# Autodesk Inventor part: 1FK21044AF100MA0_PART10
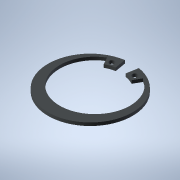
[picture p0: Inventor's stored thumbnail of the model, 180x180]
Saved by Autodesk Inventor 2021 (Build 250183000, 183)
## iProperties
Created: 2025-04
Part Number: 1FK21044AF100MA0_PART10
Material: Generic
Catalog Web Link: www.3dfindit.com
Description: -Servo synchronous motor
Document SubType Name: Modeling
Designer: psAdmin
Mass: 0.642463 g
Surface Area: 12.3927 cm^2
Volume: 0.642463 cm^3
Density: 1 g/cm^3
Appearance: PSOLRGB-212-217-219
Category: PARTsolutions
Title: 1FK21044AF100MA0_PART10
Author: Cadenas PARTsolutions
Comments: Servo synchronous motor
Sending System: PARTsolutions
Preprocessor: ST-DEVELOPER v19.3
PSOL_IDENT_0: {$CADENAS_DATA/23d-libs/siemens_ag/_cat_/ec/e4/1fk21044af100ma0.prj},216 {VTYP=3D},{NB=1FK21044AF100
PSOL_IDENT_1: MA0_PART10},{LINA=1FK21044AF100MA0_PART10},{NN=1FK21044AF100MA0_PART10},{NOPRJ=TRUE},{DATE=19.08.202
PSOL_IDENT_2: 5 14:01:05},{GEOMDATE=30.07.2025 02:01:01},{VERSION=},{LINEID=10},{WBVAR=},{WBNUMERIC=}  {NB=1FK2104
PSOL_IDENT_3: 4AF100MA0_PART10},{LINA=1FK21044AF100MA0_PART10},{KT=DUMMY},{PREVIEW=../../../_pool_/cb/72/p_d211_xx
PSOL_IDENT_4: _00434j.png},{DESCSHORT=SIMOTICS S-1FK2 HD, SINAMICS S210 3AC 400V-480V, 1.27 Nm, 3000 rpm},{DESCLON
PSOL_IDENT_5: G=SIMOTICS S-1FK2 HD servo motor M0=1.27 Nm; PN = 0.4 kW at nN=3000 rpm (380-480 V); PN = 0.2 kW at
PSOL_IDENT_6: nN=1500 rpm (200-240 V); with holding brake; degree of protection IP64; cylindrical shaft D19x40mm;
PSOL_IDENT_7: absolute encoder 22-bit + 12-bit multiturn (encoder AM22DQC); with OCC interface; plug size M17, rot
PSOL_IDENT_8: atable; SIMOTICS S-1FK2 servomotorfor a wide range of uses in industrial environments. SIMOTICS S‑1F
PSOL_IDENT_9: K2 servomotors are compact synchronous motors with a high dynamic performance that set themselves ap
PSOL_IDENT_10: art as a result of their high power density, degree of protection and overload capability. The motor
PSOL_IDENT_11: s are available in two variants: as High Dynamic variant (highest dynamic performance as a result of
PSOL_IDENT_12: the low intrinsic moment of inertia for applications demanding a high dynamic performance with low
PSOL_IDENT_13: moved masses) - and as Compact variant (precise and stable closed-loop control for medium up to larg
PSOL_IDENT_14: e moved masses as a result of a medium intrinsic moment of inertia). SIMOTICSS‑1FK2 servomotors full
PSOL_IDENT_15: y exploit their strengths in a system with the SINAMICSS210 frequency converter and simple connectio
PSOL_IDENT_16: n using the one cable connection (OCC). Advantages include the short control and positioning times,
PSOL_IDENT_17: fast and precise correction of disturbing quantities as well as stable control with a high dynamic p
PSOL_IDENT_18: erformance. The servo motors can be configured to address a wide range of requirements. For example
PSOL_IDENT_19: with and without holding brake, IP64 or IP65 degree of protection, singleturn or multiturn absolute
PSOL_IDENT_20: encoders - to name just a few. Further, the servomotors are available in different shaft heights ext
PSOL_IDENT_21: ending from 20 to 100. A shaft sealing ring is available to achieve an IP65 degree of protection and
PSOL_IDENT_22: for subsequent mounting at the motor or as spare part. SIMOTICS - the optimum motor for each and ev
PSOL_IDENT_23: ery motion control application.},{INTNO=195125043275},{SUPPLIERALTNO=1FK2104-4AF10-0MA0},{MANUID=1FK
PSOL_IDENT_24: 21044AF100MA0},{MANUNAME=Siemens},{MANUTYPEDESC=Synchronous motor 1FK2-HD 1.27 NM},{AAU732=SIMOTICS}
PSOL_IDENT_25: ,{AAO057=S-1FK2},{AAU734=SIMOTICS S-1FK2 HD servo motor M0=1.27 Nm; PN = 0.4 kW at nN=3000 rpm (380-
PSOL_IDENT_26: 480 V); PN = 0.2 kW at nN=1500 rpm (200-240 V); with holding brake; degree of protection IP64; cylin
PSOL_IDENT_27: drical shaft D19x40mm; absolute encoder 22-bit + 12-bit multiturn (encoder AM22DQC); with OCC interf
PSOL_IDENT_28: ace; plug size M17, rotatable;},{AAW338=Synchronous motor 1FK2-HD 1.27 NM},{AAO742=SIMOTICS},{AAO663=
PSOL_IDENT_29: 4042948694015},{NOCUPEROU=1},{PRICEQUANTITY=1},{QUANTITYMIN=1},{QUANTITYINT=1},{CTN=85015100},{COO=D
PSOL_IDENT_30: E},{AAO676=1FK2104-4AF10-0MA0},{AAO677=Siemens AG},{ORDERUNIT=C62},{CONTENTUNIT=C62}
NB: 1FK21044AF100MA0_PART10
NT: Servo synchronous motor
NBSYN: $MANUID._PART10
LINA: 1FK21044AF100MA0_PART10
CATALOG: SIEMENS
PREVIEW: ../../../_pool_/cb/72/p_d211_xx_00434j.png
DESCSHORT: SIMOTICS S-1FK2 HD, SINAMICS S210 3AC 400V-480V, 1.27 Nm, 3000 rpm
DESCLONG: SIMOTICS S-1FK2 HD servo motor M0=1.27 Nm; PN = 0.4 kW at nN=3000 rpm (380-480 V); PN = 0.2 kW at nN=1500 rpm (200-240 V); with holding brake; degree of protect
INTNO: 195125043275
SUPPLIERALTNO: 1FK2104-4AF10-0MA0
MANUID: 1FK21044AF100MA0
MANUNAME: Siemens
MANUTYPEDESC: Synchronous motor 1FK2-HD 1.27 NM
AAU732: SIMOTICS
AAO057: S-1FK2
AAU734: SIMOTICS S-1FK2 HD servo motor M0=1.27 Nm; PN = 0.4 kW at nN=3000 rpm (380-480 V); PN = 0.2 kW at nN=1500 rpm (200-240 V); with holding brake; degree of protect
AAW338: Synchronous motor 1FK2-HD 1.27 NM
AAO742: SIMOTICS
AAO663: 4042948694015.0
NOCUPEROU: 1
PRICEQUANTITY: 1
QUANTITYMIN: 1
QUANTITYINT: 1
CTN: 85015100
COO: DE
ARTICLENO: 1FK21044AF100MA0_PART10
BOMINFO: 1FK21044AF100MA0_PART10
CREATOR: CADENAS GmbH
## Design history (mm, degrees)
feature "2025_04_17_15_33_01_0673"
body "Solid1"
